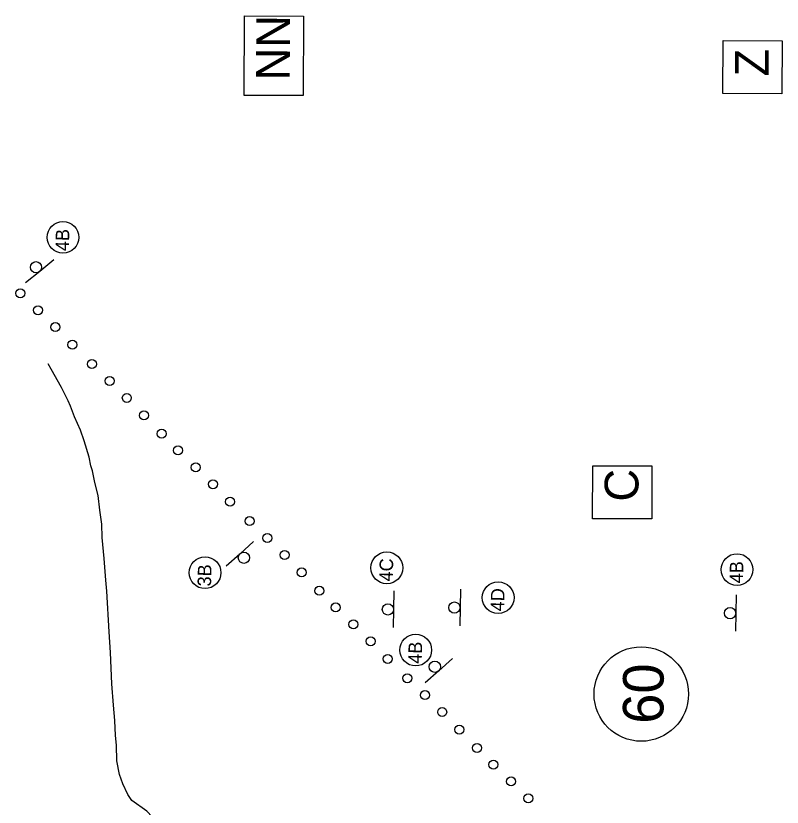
# Model space of a CAD drawing. Extents: x 311409 to 379449, y 121539 to 224848.
# Drawn here: x 336675 to 353693, y 144161 to 161729 of the extents above; entities that cross this region are included whole.
import ezdxf

# ---------------------------------------------------------------- set-up
doc = ezdxf.new("R2010")
doc.units = 0
for name, color, linetype in [('CA-TEXT', 7, 'Continuous'), ('CE-TOPO-CONC-SLAB', 7, 'Continuous'), ('Level 1', 7, 'Continuous'), ('SIGNS-POLES', 7, 'Continuous')]:
    doc.layers.add(name, color=color, linetype=linetype)

msp = doc.modelspace()

# ---------------------------------------------------------------- linework, layer by layer
at = {"layer": 'CA-TEXT'}
for p, q in [((342386, 160880), (342386, 160880)), ((353018, 160614), (353018, 160614)), ((350126, 151176), (350126, 151176)), ((350564, 146672), (350564, 146672))]:
    msp.add_line(p, q, dxfattribs=at)
for points in [[(343055, 159957), (341743, 159962), (341750, 161729), (343063, 161723)], [(353688, 159998), (352376, 160003), (352381, 161181), (353693, 161176)], [(350797, 150559), (349484, 150565), (349489, 151742), (350802, 151737)]]:
    msp.add_lwpolyline(points, close=True, dxfattribs=at)
for centre, radius in [((337722, 156810), 352), ((340879, 149365), 352), ((344914, 149474), 352), ((352690, 149435), 352), ((347386, 148812), 352), ((345556, 147648), 352), ((350564, 146672), 1048)]:
    msp.add_circle(centre, radius, dxfattribs=at)
at = {"layer": 'CE-TOPO-CONC-SLAB'}
for centre in [(336776, 155569), (337169, 155193), (337551, 154818), (337932, 154428), (338364, 153998), (338758, 153623), (339140, 153247), (339521, 152858), (339914, 152451), (340277, 152081), (340671, 151705), (341053, 151330), (341434, 150941), (341866, 150511), (342260, 150135), (342642, 149760), (343022, 149371), (343416, 148964), (343779, 148594), (344172, 148218), (344555, 147843), (344935, 147453), (345368, 147024), (345761, 146648), (346143, 146272), (346524, 145883), (346917, 145476), (347281, 145106), (347674, 144731), (348056, 144355)]:
    msp.add_circle(centre, 100, dxfattribs=at)
at = {"layer": 'Level 1'}
for points in [[(337888, 153065), (337834, 153181), (337686, 153476), (337458, 153884), (337394, 154000)], [(338339, 151739), (338304, 151933), (338194, 152290), (338109, 152528), (337980, 152823), (337888, 153065)], [(338543, 150754), (338502, 151081), (338430, 151369), (338400, 151513), (338376, 151626), (338339, 151739)], [(338749, 148053), (338695, 148954), (338672, 149198), (338639, 149680), (338594, 150149), (338584, 150443), (338543, 150754)], [(338908, 145539), (338885, 145752), (338875, 146084), (338841, 146428), (338808, 146897), (338777, 147597), (338749, 148053)], [(339166, 144443), (339050, 144682), (338977, 144889), (338917, 145189), (338908, 145539)], [(339253, 144311), (339166, 144443)], [(340066, 143483), (339923, 143711), (339582, 144071), (339253, 144311)]]:
    msp.add_lwpolyline(points, dxfattribs=at)
at = {"layer": 'SIGNS-POLES'}
for p, q in [((337521, 156312), (337209, 156054)), ((337205, 156054), (336891, 155798)), ((341654, 149788), (341956, 150057)), ((341349, 149516), (341650, 149788)), ((346548, 149001), (346543, 148596)), ((345070, 148960), (345064, 148555)), ((352669, 148878), (352664, 148473)), ((345061, 148552), (345053, 148147)), ((346540, 148594), (346532, 148189)), ((352661, 148470), (352653, 148065)), ((346373, 147458), (346070, 147189)), ((346066, 147189), (345762, 146922))]:
    msp.add_line(p, q, dxfattribs=at)
for centre in [(337123, 156148), (341740, 149698), (344937, 148550), (346416, 148591), (352536, 148468), (345980, 147279)]:
    msp.add_circle(centre, 125, dxfattribs=at)

# ---------------------------------------------------------------- texts
at = {"layer": 'CA-TEXT'}
for s, height, rotation, p in [('NN', 750, 89.767, (342759, 160294)), ('Z', 750, 89.767, (353392, 160382)), ('4B', 300, 88.8468, (337854, 156504)), ('C', 750, 89.767, (350500, 150944)), ('3B', 300, 88.8468, (341010, 149059)), ('4C', 300, 88.8468, (345046, 149168)), ('4B', 300, 88.8468, (352822, 149129)), ('4D', 300, 88.8468, (347518, 148506)), ('4B', 300, 88.8468, (345688, 147342)), ('60', 900, 89.767, (351056, 146011))]:
    msp.add_text(s, height=height, rotation=rotation, dxfattribs=at).set_placement(p)

doc.saveas('drawing.dxf')
